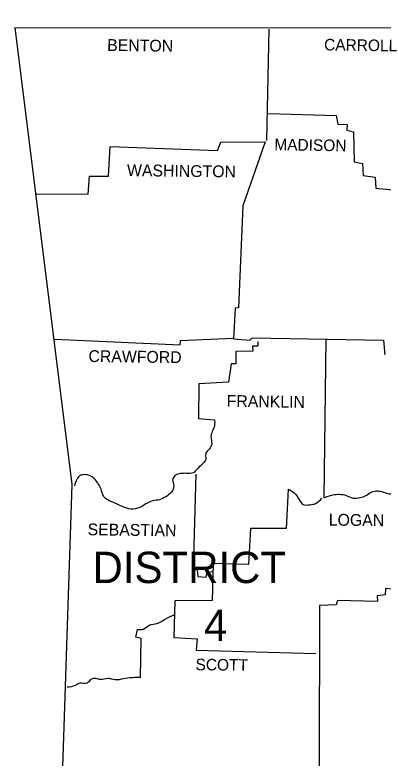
# Model space of a CAD drawing. Extents: x 3046 to 131673, y -8885 to 10756.
# Drawn here: x 101766 to 103075, y 7714 to 10358 of the extents above; entities that cross this region are included whole.
import ezdxf

# ---------------------------------------------------------------- set-up
doc = ezdxf.new("R2010")
doc.units = 0
for name, color, linetype in [('1', 7, 'Continuous'), ('2', 7, 'Continuous'), ('3', 7, 'Continuous')]:
    doc.layers.add(name, color=color, linetype=linetype)

msp = doc.modelspace()

# ---------------------------------------------------------------- linework, layer by layer
at = {"layer": '1'}
for points in [[(101766.1, 10313), (103348.2, 10312), (104736.6, 10314.9), (106374.4, 10340.4), (107133.7, 10358)], [(101766.1, 10313), (103348.2, 10312), (104736.6, 10314.9), (106374.4, 10340.4), (107133.7, 10358)], [(101766.1, 10313), (101968.7, 8686.9), (101880.6, 6032.5)], [(101766.1, 10313), (101968.7, 8686.9), (101880.6, 6032.5)], [(102669.2, 10307.1), (102660.4, 9910.9)], [(102669.2, 10307.1), (102660.4, 9910.9)], [(102667.2, 10007.7), (102907.9, 9999.9), (102913.8, 9968.6), (102947.1, 9967.6), (102946.1, 9948), (102969.6, 9942.2), (102971.5, 9835.5), (103001.9, 9828.7), (103003.8, 9786.6), (103046.9, 9780.7), (103048.8, 9741.6), (103133.9, 9732.8), (103353.1, 9737.7), (103355.1, 10300.3)], [(102667.2, 10007.7), (102907.9, 9999.9), (102913.8, 9968.6), (102947.1, 9967.6), (102946.1, 9948), (102969.6, 9942.2), (102971.5, 9835.5), (103001.9, 9828.7), (103003.8, 9786.6), (103046.9, 9780.7), (103048.8, 9741.6), (103133.9, 9732.8), (103353.1, 9737.7), (103355.1, 10300.3)], [(101843.4, 9721.1), (102026.4, 9720.1), (102031.3, 9784.6), (102098.8, 9784.6), (102104.7, 9889.3), (102486.2, 9875.6), (102498, 9905), (102655.5, 9906), (102576.2, 9679), (102560.6, 9316), (102548.9, 9315), (102543, 9205.4), (102600.7, 9200.5), (102609.5, 9209.3), (103076.2, 9200.5), (103081.1, 9148.7)], [(101843.4, 9721.1), (102026.4, 9720.1), (102031.3, 9784.6), (102098.8, 9784.6), (102104.7, 9889.3), (102486.2, 9875.6), (102498, 9905), (102655.5, 9906), (102576.2, 9679), (102560.6, 9316), (102548.9, 9315), (102543, 9205.4), (102600.7, 9200.5), (102609.5, 9209.3), (103076.2, 9200.5), (103081.1, 9148.7)], [(101908, 9204.5), (102353.2, 9183.9), (102355.1, 9199.6), (102541, 9208.4)], [(101908, 9204.5), (102353.2, 9183.9), (102355.1, 9199.6), (102541, 9208.4)], [(102870.7, 9204.5), (102863.9, 8639.9)], [(102870.7, 9204.5), (102863.9, 8639.9)], [(102629.1, 9196.6), (102629.1, 9179), (102610.5, 9179), (102611.5, 9161.4), (102551.8, 9160.4), (102550.8, 9116.4), (102534.2, 9116.4), (102525.4, 9050.8), (102419.7, 9046), (102418.7, 8921.7), (102475.5, 8917.8)], [(102629.1, 9196.6), (102629.1, 9179), (102610.5, 9179), (102611.5, 9161.4), (102551.8, 9160.4), (102550.8, 9116.4), (102534.2, 9116.4), (102525.4, 9050.8), (102419.7, 9046), (102418.7, 8921.7), (102475.5, 8917.8)], [(102408.9, 8724.1), (102399.2, 8387.5), (102413.8, 8383.6), (102416.8, 8360.1), (102446.1, 8358.1), (102449.1, 8374.8), (102472.5, 8378.7)], [(102408.9, 8724.1), (102399.2, 8387.5), (102413.8, 8383.6), (102416.8, 8360.1), (102446.1, 8358.1), (102449.1, 8374.8), (102472.5, 8378.7)], [(102737.7, 8671.2), (102730.8, 8531.3), (102603.6, 8530.3), (102596.8, 8403.1), (102470.6, 8406.1), (102466.7, 8275), (102334.6, 8274), (102330.7, 8142.9), (102413.8, 8138), (102410.9, 8097.9), (102835.5, 8086.1)], [(102737.7, 8671.2), (102730.8, 8531.3), (102603.6, 8530.3), (102596.8, 8403.1), (102470.6, 8406.1), (102466.7, 8275), (102334.6, 8274), (102330.7, 8142.9), (102413.8, 8138), (102410.9, 8097.9), (102835.5, 8086.1)], [(103380.5, 8521.5), (103376.6, 8380.6), (103153.5, 8379.7), (103124.2, 8354.2), (103107.5, 8315.1), (103083.1, 8317), (103082.1, 8294.5), (103053.7, 8291.6), (103054.7, 8271.1), (102912.8, 8275), (102907.9, 8259.3), (102849.2, 8257.4), (102847.3, 7685)], [(103380.5, 8521.5), (103376.6, 8380.6), (103153.5, 8379.7), (103124.2, 8354.2), (103107.5, 8315.1), (103083.1, 8317), (103082.1, 8294.5), (103053.7, 8291.6), (103054.7, 8271.1), (102912.8, 8275), (102907.9, 8259.3), (102849.2, 8257.4), (102847.3, 7685)], [(102212.3, 8001), (102215.2, 8139), (102195.6, 8144.8), (102201.5, 8171.3)], [(102212.3, 8001), (102215.2, 8139), (102195.6, 8144.8), (102201.5, 8171.3)]]:
    msp.add_lwpolyline(points, dxfattribs=at)
for points in [[(102475.5, 8917.8), (102475.5, 8897.2), (102467.6, 8875.7), (102462.8, 8857.1), (102465.7, 8832.7), (102456.9, 8813.1), (102444.2, 8797.4), (102444.2, 8777.9), (102429.5, 8757.3), (102413.8, 8741.7), (102400.1, 8728.9), (102375.7, 8727), (102355.1, 8726), (102334.6, 8719.2), (102326.8, 8704.5), (102330.7, 8682), (102322.8, 8660.5), (102302.3, 8643.8), (102279.8, 8633.1), (102256.3, 8629.2), (102224, 8613.5), (102194.7, 8600.8), (102163.4, 8602.7), (102134, 8615.5), (102107.6, 8627.2), (102087, 8638.9), (102070.4, 8675.1), (102059.6, 8694.7), (102041.1, 8714.3), (102018.6, 8722.1), (102000, 8720.1), (101977.5, 8682)], [(102475.5, 8917.8), (102475.5, 8897.2), (102467.6, 8875.7), (102462.8, 8857.1), (102465.7, 8832.7), (102456.9, 8813.1), (102444.2, 8797.4), (102444.2, 8777.9), (102429.5, 8757.3), (102413.8, 8741.7), (102400.1, 8728.9), (102375.7, 8727), (102355.1, 8726), (102334.6, 8719.2), (102326.8, 8704.5), (102330.7, 8682), (102322.8, 8660.5), (102302.3, 8643.8), (102279.8, 8633.1), (102256.3, 8629.2), (102224, 8613.5), (102194.7, 8600.8), (102163.4, 8602.7), (102134, 8615.5), (102107.6, 8627.2), (102087, 8638.9), (102070.4, 8675.1), (102059.6, 8694.7), (102041.1, 8714.3), (102018.6, 8722.1), (102000, 8720.1), (101977.5, 8682)], [(102863.9, 8639.9), (102896.2, 8650.7), (102919.7, 8652.6), (102943.1, 8648.7), (102967.6, 8638.9), (102994, 8640.9), (103013.6, 8647.7), (103033.2, 8660.5), (103054.7, 8664.4), (103075.2, 8660.5), (103096.8, 8654.6), (103120.2, 8661.4), (103133.9, 8674.2), (103157.4, 8678.1), (103178, 8678.1), (103192.6, 8661.4), (103195.6, 8643.8), (103214.2, 8627.2), (103230.8, 8616.4), (103235.7, 8595.9), (103244.5, 8581.2), (103253.3, 8571.4), (103266, 8565.6), (103287.5, 8567.5), (103320.8, 8560.7), (103342.3, 8555.8), (103361.9, 8539.1), (103380.5, 8521.5)], [(102863.9, 8639.9), (102896.2, 8650.7), (102919.7, 8652.6), (102943.1, 8648.7), (102967.6, 8638.9), (102994, 8640.9), (103013.6, 8647.7), (103033.2, 8660.5), (103054.7, 8664.4), (103075.2, 8660.5), (103096.8, 8654.6), (103120.2, 8661.4), (103133.9, 8674.2), (103157.4, 8678.1), (103178, 8678.1), (103192.6, 8661.4), (103195.6, 8643.8), (103214.2, 8627.2), (103230.8, 8616.4), (103235.7, 8595.9), (103244.5, 8581.2), (103253.3, 8571.4), (103266, 8565.6), (103287.5, 8567.5), (103320.8, 8560.7), (103342.3, 8555.8), (103361.9, 8539.1), (103380.5, 8521.5)], [(102737.7, 8671.2), (102759.2, 8657.5), (102775.8, 8635), (102790.5, 8616.4), (102815, 8615.5), (102834.5, 8619.4), (102857, 8638.9)], [(102737.7, 8671.2), (102759.2, 8657.5), (102775.8, 8635), (102790.5, 8616.4), (102815, 8615.5), (102834.5, 8619.4), (102857, 8638.9)], [(102201.5, 8171.3), (102223, 8173.2), (102243.6, 8186.9), (102271, 8192.8), (102298.4, 8207.5), (102332.6, 8223.1)], [(102201.5, 8171.3), (102223, 8173.2), (102243.6, 8186.9), (102271, 8192.8), (102298.4, 8207.5), (102332.6, 8223.1)], [(102212.3, 8001), (102183.9, 8000), (102151.6, 7996.1), (102122.3, 7992.2), (102095.8, 7997.1), (102071.4, 7993.2), (102054.8, 7997.1), (102034.2, 7992.2), (102022.5, 7980.5), (101998, 7980.5), (101980.4, 7972.6), (101952, 7965.8)], [(102212.3, 8001), (102183.9, 8000), (102151.6, 7996.1), (102122.3, 7992.2), (102095.8, 7997.1), (102071.4, 7993.2), (102054.8, 7997.1), (102034.2, 7992.2), (102022.5, 7980.5), (101998, 7980.5), (101980.4, 7972.6), (101952, 7965.8)]]:
    msp.add_spline(points, degree=3, dxfattribs=at)

# ---------------------------------------------------------------- texts
at = {"layer": '2'}
for s, height, rotation, p in [('BENTON', 42.07, 359.2527, (102093.9, 10229.8)), ('BENTON', 42.07, 359.2527, (102093.9, 10229.8)), ('CARROLL', 41.09, 359.1481, (102864.9, 10231.8)), ('CARROLL', 41.09, 359.1481, (102864.9, 10231.8)), ('MADISON', 41.09, 359.0906, (102687.8, 9876.6)), ('MADISON', 41.09, 359.0906, (102687.8, 9876.6)), ('WASHINGTON', 42.06, 359.232, (102164.3, 9784.6)), ('WASHINGTON', 42.06, 359.232, (102164.3, 9784.6)), ('CRAWFORD', 42.06, 359.2771, (102027.4, 9123.2)), ('CRAWFORD', 42.06, 359.2771, (102027.4, 9123.2)), ('FRANKLIN', 42.07, 359.1815, (102518.5, 8963.8)), ('FRANKLIN', 42.07, 359.1815, (102518.5, 8963.8)), ('LOGAN', 42.07, 359.3969, (102881.5, 8541.1)), ('LOGAN', 42.07, 359.3969, (102881.5, 8541.1)), ('SEBASTIAN', 42.06, 359.2816, (102024.4, 8506.8)), ('SEBASTIAN', 42.06, 359.2816, (102024.4, 8506.8)), ('SCOTT', 41.09, 359.4063, (102408, 8026.5)), ('SCOTT', 41.09, 359.4063, (102408, 8026.5))]:
    msp.add_text(s, height=height, rotation=rotation, dxfattribs=at).set_placement(p)
at = {"layer": '3'}
for s, height, p in [('DISTRICT', 111.54, (102042, 8336.6)), ('DISTRICT', 111.54, (102042, 8336.6)), ('4', 111.5, (102438.3, 8131.1)), ('4', 111.5, (102438.3, 8131.1))]:
    msp.add_text(s, height=height, dxfattribs=at).set_placement(p)

doc.saveas('drawing.dxf')
